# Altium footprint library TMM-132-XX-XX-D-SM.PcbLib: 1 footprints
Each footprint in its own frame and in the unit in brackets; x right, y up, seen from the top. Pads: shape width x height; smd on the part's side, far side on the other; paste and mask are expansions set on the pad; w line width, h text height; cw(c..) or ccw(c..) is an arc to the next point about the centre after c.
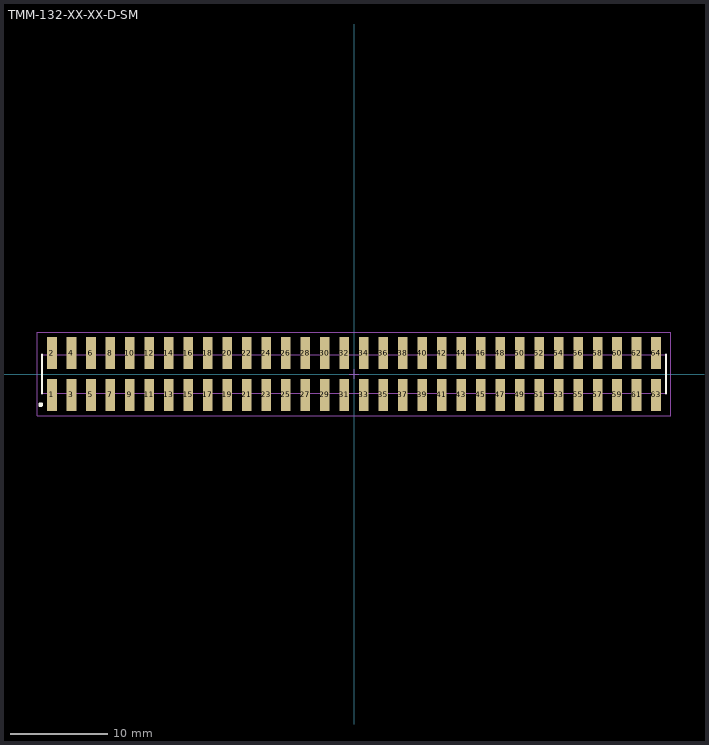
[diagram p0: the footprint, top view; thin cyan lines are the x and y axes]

## TMM-132-XX-XX-D-SM [mm] "2.00mm pitch, 64 pin, terminal strip; double row, SMT"
height 2.77
pads (64):
  rect 1x3.3 smd mask+0: 1(-31,-2.15) 2(-31,2.15) 3(-29,-2.15) 4(-29,2.15) 5(-27,-2.15) 6(-27,2.15) 7(-25,-2.15) 8(-25,2.15) 9(-23,-2.15) 10(-23,2.15) 11(-21,-2.15) 12(-21,2.15) 13(-19,-2.15) 14(-19,2.15) 15(-17,-2.15) 16(-17,2.15) 17(-15,-2.15) 18(-15,2.15) 19(-13,-2.15) 20(-13,2.15) 21(-11,-2.15) 22(-11,2.15) 23(-9,-2.15) 24(-9,2.15) 25(-7,-2.15) 26(-7,2.15) 27(-5,-2.15) 28(-5,2.15) 29(-3,-2.15) 30(-3,2.15) 31(-1,-2.15) 32(-1,2.15) 33(1,-2.15) 34(1,2.15) 35(3,-2.15) 36(3,2.15) 37(5,-2.15) 38(5,2.15) 39(7,-2.15) 40(7,2.15) 41(9,-2.15) 42(9,2.15) 43(11,-2.15) 44(11,2.15) 45(13,-2.15) 46(13,2.15) 47(15,-2.15) 48(15,2.15) 49(17,-2.15) 50(17,2.15) 51(19,-2.15) 52(19,2.15) 53(21,-2.15) 54(21,2.15) 55(23,-2.15) 56(23,2.15) 57(25,-2.15) 58(25,2.15) 59(27,-2.15) 60(27,2.15) 61(29,-2.15) 62(29,2.15) 63(31,-2.15) 64(31,2.15)
Top Overlay:
  circle w0.25: c-32.15,-3.15 r0.125
  lines w0.2: -32,-2 -32,2 ; 32,-2 32,2
Mechanical 12:
  lines w0.001: -32,-2 32,-2 32,2 -32,2 -32,-2
Mechanical 13:
  lines w0.1: -32,-2 32,-2 32,2 -32,2 -32,-2
  text ".Designator" at 0.127,-0.127 h1.52
Mechanical 15:
  lines w0.05: -0.5,0 0.5,0 ; 0,-0.5 0,0.5 ; -32.5,-4.3 32.5,-4.3 32.5,4.3 -32.5,4.3 -32.5,-4.3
